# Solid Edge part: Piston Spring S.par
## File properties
Author: Dan
Template: Piston Spring.par
Last saved by: Dan
Revision: 2
Application: Solid Edge
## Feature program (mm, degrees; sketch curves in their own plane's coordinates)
body "unnamed Body 1"
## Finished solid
Body 1: solid body, 12 faces, 14 edges, 4 vertices.
  Faces by surface: spline 8, cylinder 2, plane 2
  Edges by curve: intersection 8, circle 4, curve on surface 2
Bounding box of the edges (mm; curved faces can reach further): 76.800 x 14.100 x 14.100, from (-24.7902, -7.05, -7.05) to (52.01, 7.05, 7.05).
Cylindrical faces by radius (mm): R5.245 x1, R7.05 x1
Planar faces by outward normal: +x 1, -x 1
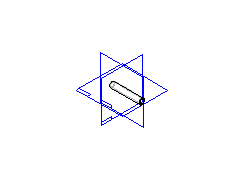
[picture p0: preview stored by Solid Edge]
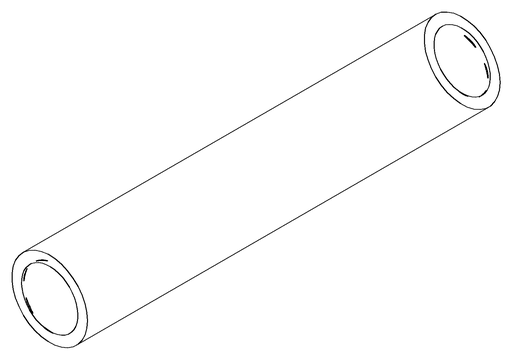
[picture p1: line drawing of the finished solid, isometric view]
